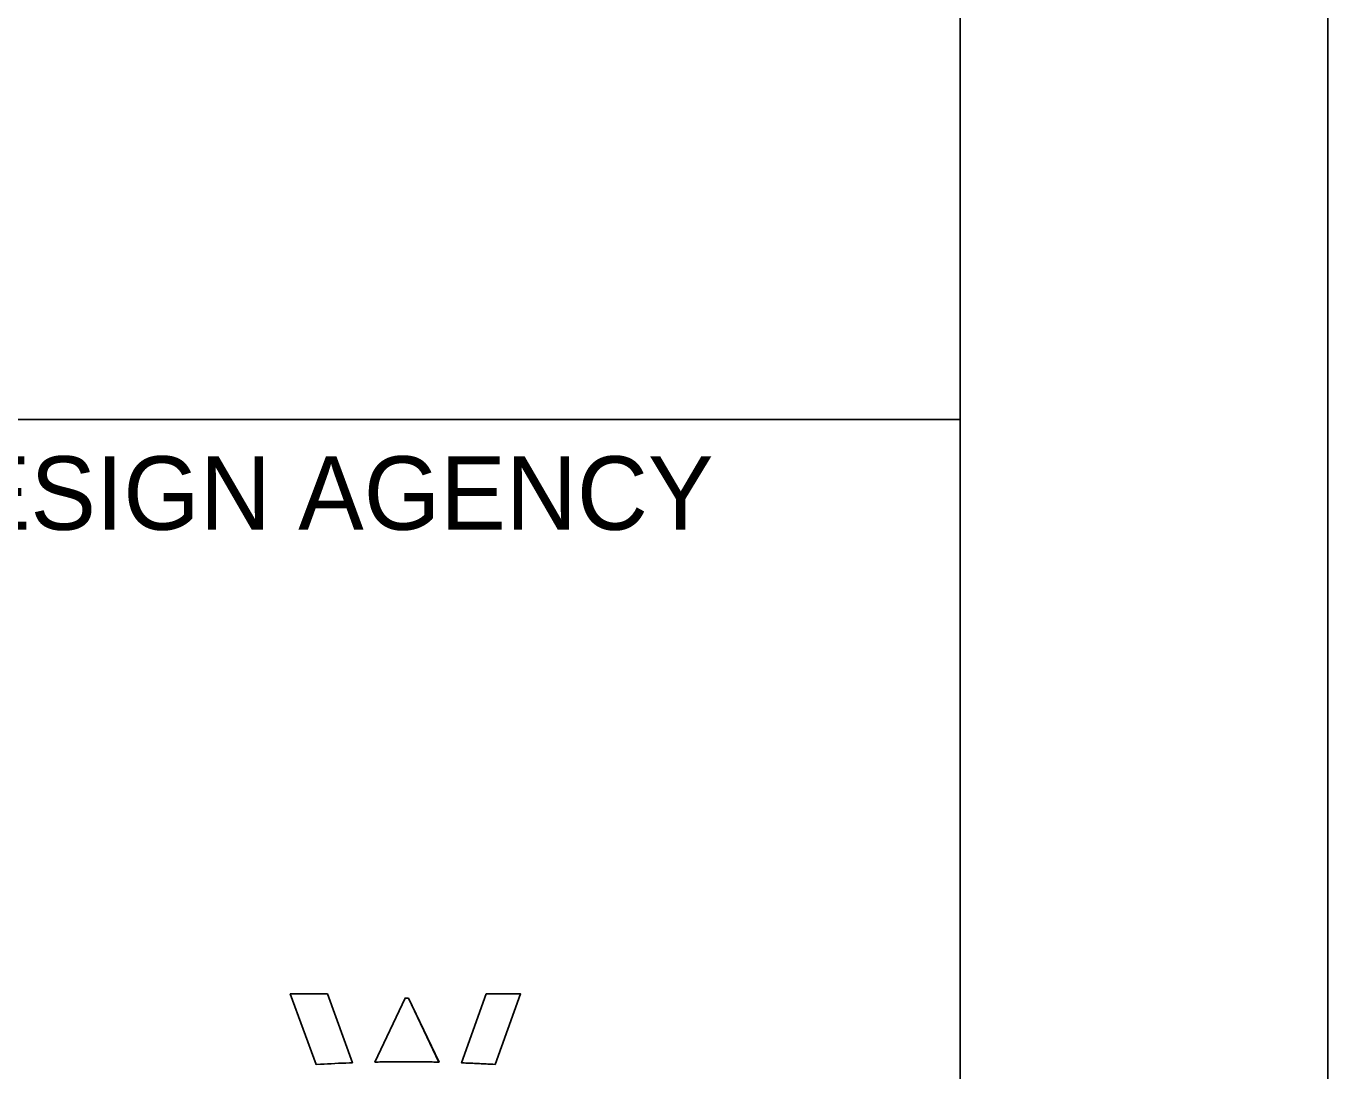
# Model space of a CAD drawing. Extents: x 0 to 34, y 0 to 22.
# Drawn here: x 32.23 to 34, y 4.114 to 5.535 of the extents above; entities that cross this region are included whole.
import ezdxf

# ---------------------------------------------------------------- set-up
doc = ezdxf.new("R2010")
doc.units = 0
for name, color, linetype in [('SH_Border', 7, 'Continuous'), ('SH_Cut_Line', 7, 'Continuous'), ('SH_Data', 7, 'Continuous'), ('SH_Text', 7, 'Continuous')]:
    doc.layers.add(name, color=color, linetype=linetype)

msp = doc.modelspace()

# ---------------------------------------------------------------- linework, layer by layer
at = {"layer": 'SH_Border'}
msp.add_line((32, 5), (33.5, 5), dxfattribs=at)
msp.add_lwpolyline([(1.5, 21.5), (33.5, 21.5), (33.5, 0.5), (1.5, 0.5)], close=True, dxfattribs=at)
at = {"layer": 'SH_Cut_Line'}
msp.add_lwpolyline([(0, 0), (34, 0), (34, 22), (0, 22)], close=True, dxfattribs=at)
at = {"layer": 'SH_Text'}
for points in [[(32.6397, 4.2186), (32.5891, 4.2186), (32.6242, 4.1226), (32.6302, 4.1229), (32.635, 4.1232), (32.6399, 4.1235), (32.6448, 4.1237), (32.6497, 4.124), (32.6547, 4.1242), (32.6597, 4.1244), (32.6647, 4.1246), (32.6697, 4.1248), (32.6736, 4.125)], [(32.8556, 4.2186), (32.822, 4.1248), (32.8232, 4.1248), (32.8255, 4.1247), (32.8279, 4.1246), (32.8302, 4.1245), (32.8325, 4.1244), (32.8348, 4.1243), (32.8371, 4.1242), (32.8394, 4.1241), (32.8417, 4.124), (32.844, 4.1239), (32.8463, 4.1238), (32.8486, 4.1237), (32.8508, 4.1236), (32.8531, 4.1234), (32.8554, 4.1233), (32.8576, 4.1232), (32.8598, 4.1231), (32.8621, 4.1229), (32.8643, 4.1228), (32.8676, 4.1226), (32.9022, 4.2186)], [(32.7499, 4.213), (32.7451, 4.213), (32.7042, 4.1259), (32.7045, 4.1259), (32.7067, 4.1259), (32.7088, 4.1259), (32.711, 4.126), (32.7132, 4.126), (32.7154, 4.1261), (32.7175, 4.1261), (32.7197, 4.1261), (32.7219, 4.1261), (32.7241, 4.1262), (32.7263, 4.1262), (32.7285, 4.1262), (32.7307, 4.1262), (32.733, 4.1262), (32.7352, 4.1263), (32.7374, 4.1263), (32.7396, 4.1263), (32.7419, 4.1263), (32.7441, 4.1263), (32.7464, 4.1263), (32.7488, 4.1263), (32.7512, 4.1263), (32.7536, 4.1263), (32.7559, 4.1263), (32.7583, 4.1263), (32.7607, 4.1262), (32.7631, 4.1262), (32.7654, 4.1262), (32.7678, 4.1262), (32.7701, 4.1261), (32.7725, 4.1261), (32.7748, 4.1261), (32.7772, 4.1261), (32.7795, 4.126), (32.7818, 4.126), (32.7842, 4.1259), (32.7865, 4.1259), (32.7888, 4.1258), (32.7911, 4.1258), (32.7915, 4.1258)]]:
    msp.add_lwpolyline(points, close=True, dxfattribs=at)
for points in [[(32.6397, 4.2186), (32.5891, 4.2186), (32.6242, 4.1226), (32.6302, 4.1229), (32.635, 4.1232), (32.6399, 4.1235), (32.6448, 4.1237), (32.6497, 4.124), (32.6547, 4.1242), (32.6597, 4.1244), (32.6647, 4.1246), (32.6697, 4.1248), (32.6736, 4.125), (32.6397, 4.2186)], [(32.8556, 4.2186), (32.822, 4.1248), (32.8232, 4.1248), (32.8255, 4.1247), (32.8279, 4.1246), (32.8302, 4.1245), (32.8325, 4.1244), (32.8348, 4.1243), (32.8371, 4.1242), (32.8394, 4.1241), (32.8417, 4.124), (32.844, 4.1239), (32.8463, 4.1238), (32.8486, 4.1237), (32.8508, 4.1236), (32.8531, 4.1234), (32.8554, 4.1233), (32.8576, 4.1232), (32.8598, 4.1231), (32.8621, 4.1229), (32.8643, 4.1228), (32.8676, 4.1226), (32.9022, 4.2186), (32.8556, 4.2186)], [(32.7499, 4.213), (32.7451, 4.213), (32.7042, 4.1259), (32.7067, 4.1259), (32.7088, 4.1259), (32.711, 4.126), (32.7132, 4.126), (32.7154, 4.1261), (32.7175, 4.1261), (32.7197, 4.1261), (32.7219, 4.1261), (32.7241, 4.1262), (32.7263, 4.1262), (32.7285, 4.1262), (32.7307, 4.1262), (32.733, 4.1262), (32.7352, 4.1263), (32.7374, 4.1263), (32.7396, 4.1263), (32.7419, 4.1263), (32.7441, 4.1263), (32.7464, 4.1263), (32.7488, 4.1263), (32.7512, 4.1263), (32.7536, 4.1263), (32.7559, 4.1263), (32.7583, 4.1263), (32.7607, 4.1262), (32.7631, 4.1262), (32.7654, 4.1262), (32.7678, 4.1262), (32.7701, 4.1261), (32.7725, 4.1261), (32.7748, 4.1261), (32.7772, 4.1261), (32.7795, 4.126), (32.7818, 4.126), (32.7842, 4.1259), (32.7865, 4.1259), (32.7888, 4.1258), (32.7911, 4.1258), (32.7499, 4.213)]]:
    msp.add_lwpolyline(points, dxfattribs=at)

# ---------------------------------------------------------------- texts
at = {"layer": 'SH_Data'}
msp.add_text('DESIGN AGENCY', height=0.1, dxfattribs=at).set_placement((32.05, 4.85))

doc.saveas('drawing.dxf')
